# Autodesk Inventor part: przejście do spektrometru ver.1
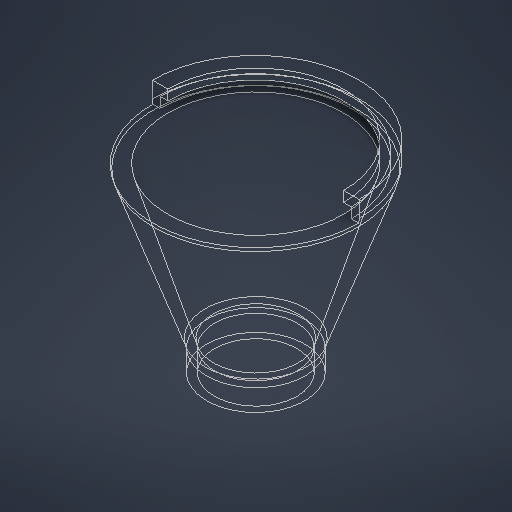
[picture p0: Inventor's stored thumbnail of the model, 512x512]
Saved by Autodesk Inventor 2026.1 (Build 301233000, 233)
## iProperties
Created: 2026-07
Part Number: przejście do spektrometru ver.1
Material: Ogólny
Document SubType Name: Modeling
Designer: Dell
Density: 1 g/cm^3
Appearance: Domyślna
Author: Dell
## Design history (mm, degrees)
sketch "Szkic1"
  geometry: C1 r 8 at (0, 0); C2 r 9.5 at (0, 0); 1 further point
  constraints: 2 centre point, 1 coincident
  dimensions: "d0" = 16 diameter of C1; "d1" = 1.5 radial gap between concentric circles of C1 C2
extrude "Wyciągnięcie proste1" new body sketch "Szkic1" distance "d2" = 5; taper "d3" = 0 deg
sketch "Szkic2"
  geometry: L1 (5, -9.5)-(5, 9.5) reference; L2 (5, 0)-(35, 0); L3 (35, 0)-(35, -17); L4 (35, -17)-(5, -8); L5 (35, -17)-(35, -18.5); L6 (35, -18.5)-(5, -9.5); L7 (35, 0)-(35, -18.5); L8 (35, -18.5)-(37, -18.5); L9 (37, -18.5)-(37, -20); L10 (37, -20)-(35, -20); L11 (35, -20)-(35, -18.5); L12 (35, -20)-(5, -9.5); L13 (37, -18.5)-(37, -17); L14 (37, -17)-(39, -17); L15 (39, -17)-(39, -20); L16 (39, -20)-(37, -20); 1 further point
  constraints: 30 end point, 8 perpendicular, 2 point on line, 2 vertical, 1 collinear, 1 horizontal, 1 midpoint
  dimensions: "d4" = 30 distance of L2.start L2.end; "d5" = 17 distance of L2.end L3.end; "d6" = 1.5 distance of L3.end L5.end; "d7" = 18.5 distance of L2.end L5.end (derived); "d8" = 2 distance of L5.end L8.end; "d9" = 1.5 distance of L8.end L9.end
revolve "Obrót1" sketch "Szkic2" stored, may be unused: angle "d10" = 90 deg
fillet "Zaokrąglenie1" dims "d11" = 5
sketch "Szkic3"
  geometry: L1 (21, 0)-(-24, 0); L2 (-24, 0)-(-24, -23); L3 (-24, -23)-(21, -23); L4 (21, -23)-(21, 0); 1 further point
  constraints: 8 end point, 2 parallel, 1 horizontal, 1 perpendicular
extrude "Wyciągnięcie proste2" cut sketch "Szkic3" distance "d12" = 4; taper "d13" = 0 deg
node "Bryła1"
